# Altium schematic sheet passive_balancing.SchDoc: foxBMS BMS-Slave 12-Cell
size A3; DocumentNumber: 5; SheetNumber: 5; SheetTotal: 15; AUTHOR: Fraunhofer IISB foxBMS Team; SheetDescription: Passive Cell Balancing
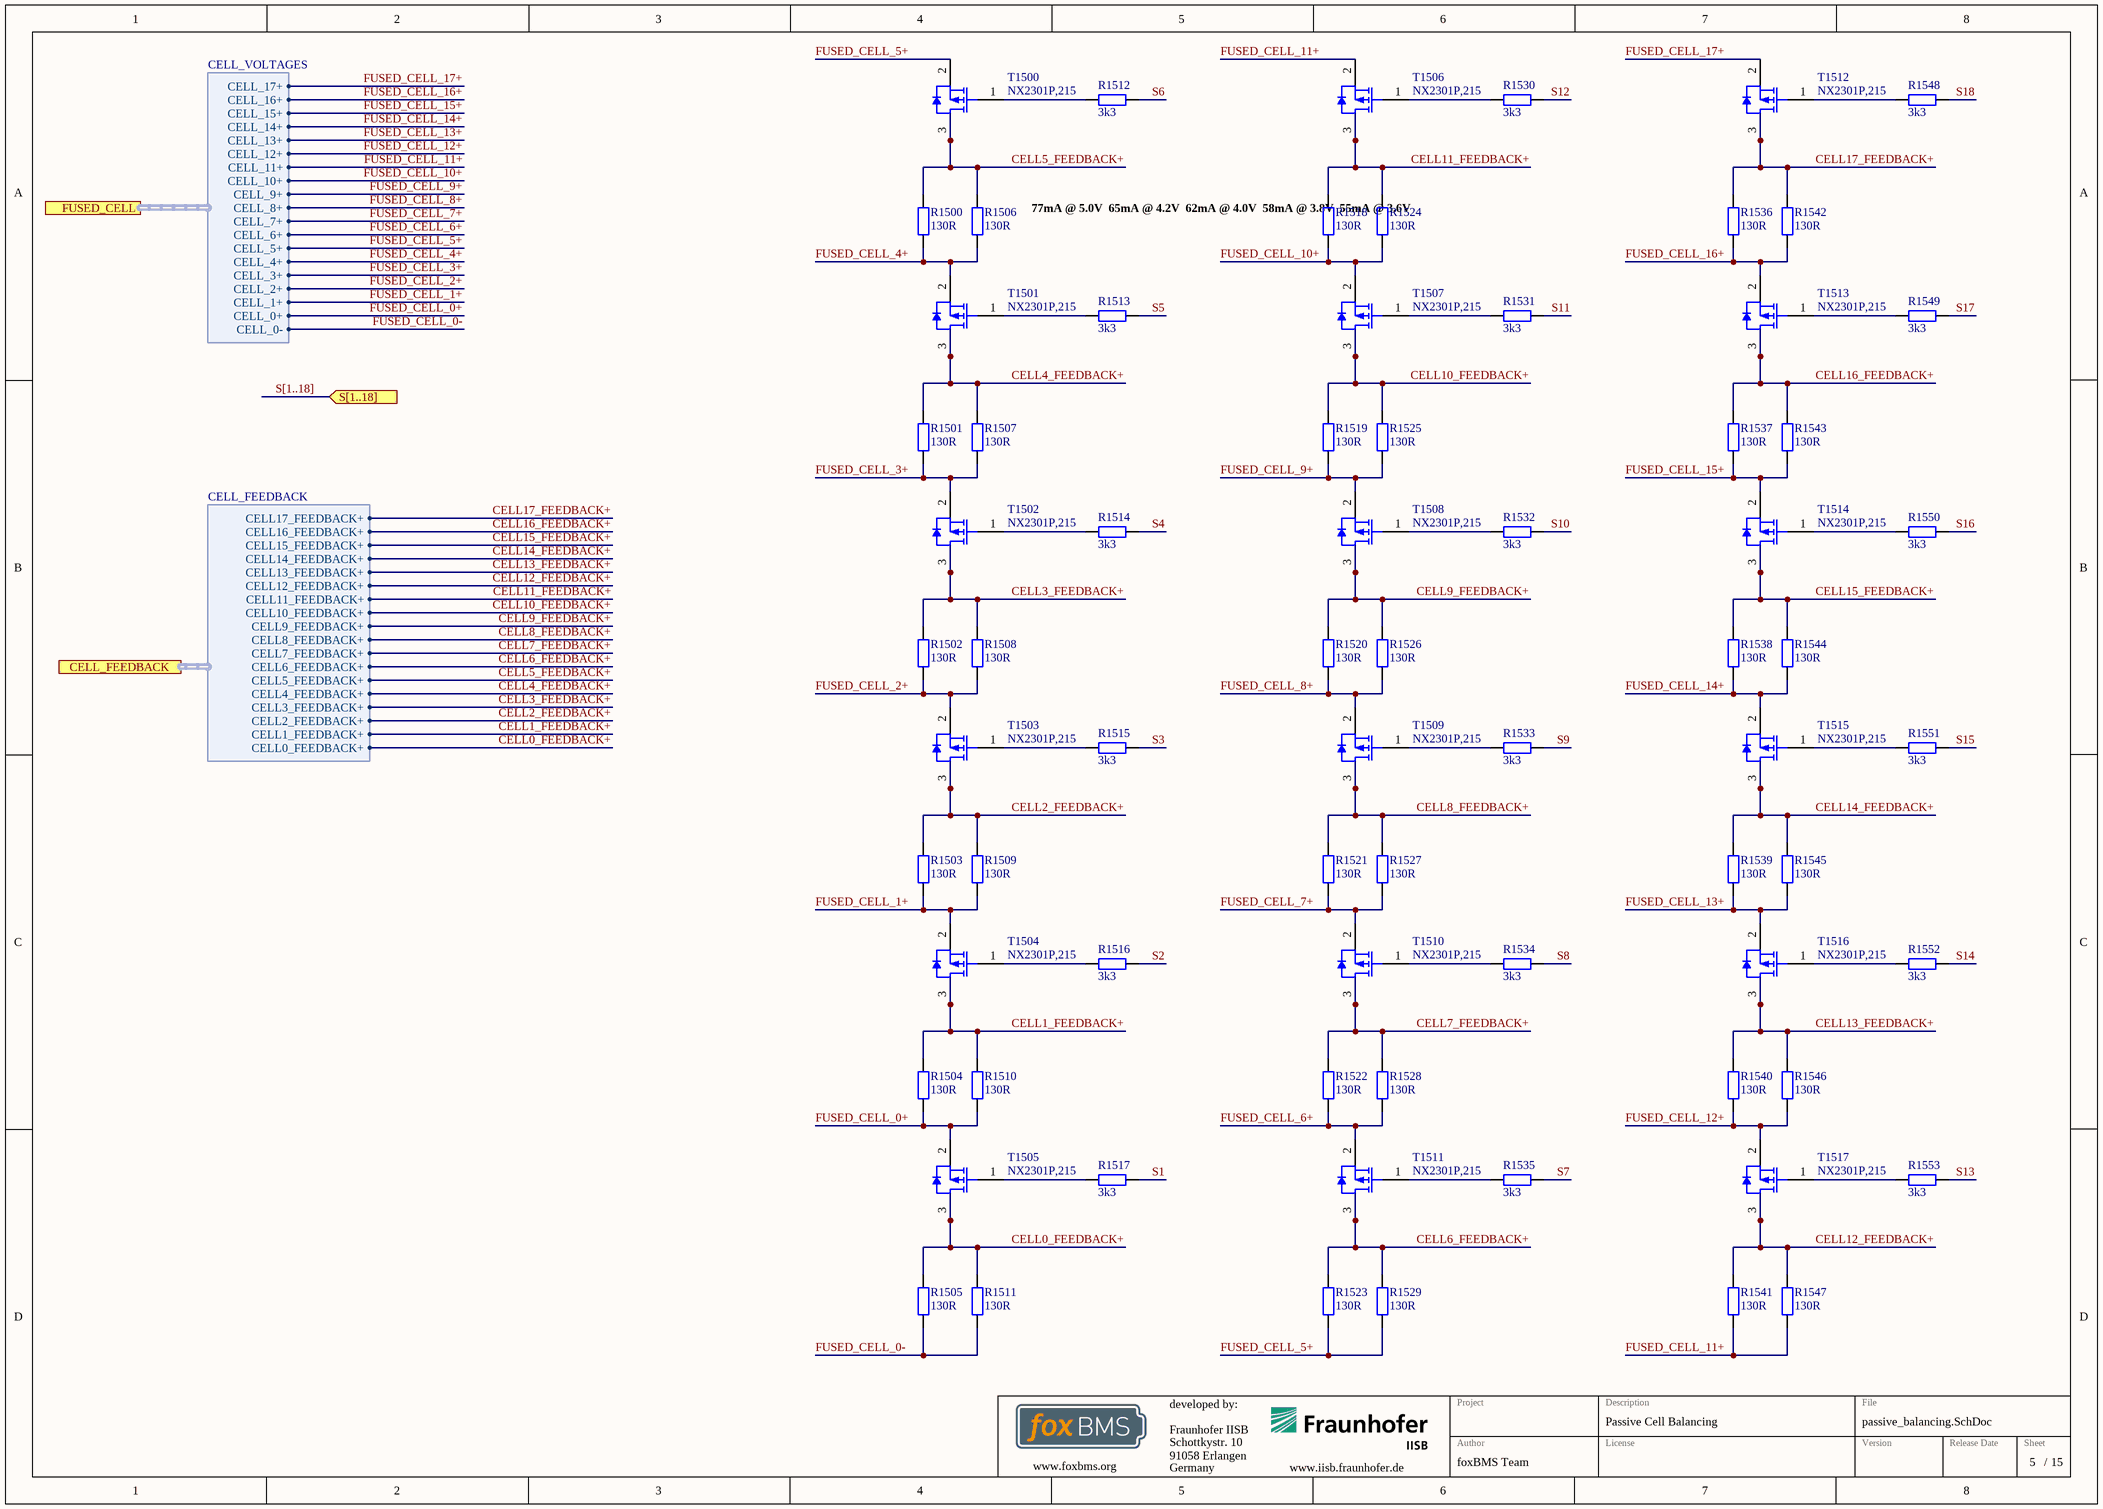
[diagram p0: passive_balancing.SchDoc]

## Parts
R1500  130R  [RESC5025X07N]
R1501  130R  [RESC5025X07N]
R1502  130R  [RESC5025X07N]
R1503  130R  [RESC5025X07N]
R1504  130R  [RESC5025X07N]
R1505  130R  [RESC5025X07N]
R1506  130R  [RESC5025X07N]
R1507  130R  [RESC5025X07N]
R1508  130R  [RESC5025X07N]
R1509  130R  [RESC5025X07N]
R1510  130R  [RESC5025X07N]
R1511  130R  [RESC5025X07N]
R1512  3k3  [RESC1608X05N]
R1513  3k3  [RESC1608X05N]
R1514  3k3  [RESC1608X05N]
R1515  3k3  [RESC1608X05N]
R1516  3k3  [RESC1608X05N]
R1517  3k3  [RESC1608X05N]
R1518  130R  [RESC5025X07N]
R1519  130R  [RESC5025X07N]
R1520  130R  [RESC5025X07N]
R1521  130R  [RESC5025X07N]
R1522  130R  [RESC5025X07N]
R1523  130R  [RESC5025X07N]
R1524  130R  [RESC5025X07N]
R1525  130R  [RESC5025X07N]
R1526  130R  [RESC5025X07N]
R1527  130R  [RESC5025X07N]
R1528  130R  [RESC5025X07N]
R1529  130R  [RESC5025X07N]
R1530  3k3  [RESC1608X05N]
R1531  3k3  [RESC1608X05N]
R1532  3k3  [RESC1608X05N]
R1533  3k3  [RESC1608X05N]
R1534  3k3  [RESC1608X05N]
R1535  3k3  [RESC1608X05N]
R1536  130R  [RESC5025X07N]
R1537  130R  [RESC5025X07N]
R1538  130R  [RESC5025X07N]
R1539  130R  [RESC5025X07N]
R1540  130R  [RESC5025X07N]
R1541  130R  [RESC5025X07N]
R1542  130R  [RESC5025X07N]
R1543  130R  [RESC5025X07N]
R1544  130R  [RESC5025X07N]
R1545  130R  [RESC5025X07N]
R1546  130R  [RESC5025X07N]
R1547  130R  [RESC5025X07N]
R1548  3k3  [RESC1608X05N]
R1549  3k3  [RESC1608X05N]
R1550  3k3  [RESC1608X05N]
R1551  3k3  [RESC1608X05N]
R1552  3k3  [RESC1608X05N]
R1553  3k3  [RESC1608X05N]
T1500  NX2301P,215  [NXP-SOT23_N]
T1501  NX2301P,215  [NXP-SOT23_N]
T1502  NX2301P,215  [NXP-SOT23_N]
T1503  NX2301P,215  [NXP-SOT23_N]
T1504  NX2301P,215  [NXP-SOT23_N]
T1505  NX2301P,215  [NXP-SOT23_N]
T1506  NX2301P,215  [NXP-SOT23_N]
T1507  NX2301P,215  [NXP-SOT23_N]
T1508  NX2301P,215  [NXP-SOT23_N]
T1509  NX2301P,215  [NXP-SOT23_N]
T1510  NX2301P,215  [NXP-SOT23_N]
T1511  NX2301P,215  [NXP-SOT23_N]
T1512  NX2301P,215  [NXP-SOT23_N]
T1513  NX2301P,215  [NXP-SOT23_N]
T1514  NX2301P,215  [NXP-SOT23_N]
T1515  NX2301P,215  [NXP-SOT23_N]
T1516  NX2301P,215  [NXP-SOT23_N]
T1517  NX2301P,215  [NXP-SOT23_N]

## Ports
CELL_FEEDBACK (harness CELL_FEEDBACK), FUSED_CELL (harness CELL_VOLTAGES), S[1..18] (in)

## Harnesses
CELL_FEEDBACK: CELL11_FEEDBACK+, CELL10_FEEDBACK+, CELL9_FEEDBACK+, CELL8_FEEDBACK+, CELL7_FEEDBACK+, CELL6_FEEDBACK+, CELL5_FEEDBACK+, CELL4_FEEDBACK+, CELL3_FEEDBACK+, CELL2_FEEDBACK+, CELL1_FEEDBACK+, CELL0_FEEDBACK+, CELL12_FEEDBACK+, CELL13_FEEDBACK+, CELL14_FEEDBACK+, CELL15_FEEDBACK+, CELL16_FEEDBACK+, CELL17_FEEDBACK+
CELL_VOLTAGES: CELL_0-, CELL_0+, CELL_1+, CELL_10+, CELL_11+, CELL_12+, CELL_13+, CELL_14+, CELL_15+, CELL_16+, CELL_17+, CELL_2+, CELL_3+, CELL_4+, CELL_5+, CELL_6+, CELL_7+, CELL_8+, CELL_9+

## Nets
CELL0_FEEDBACK+: R1505.2 R1511.2 T1505.3(D) ; port CELL_FEEDBACK.CELL0_FEEDBACK+
CELL1_FEEDBACK+: R1504.2 R1510.2 T1504.3(D) ; port CELL_FEEDBACK.CELL1_FEEDBACK+
CELL2_FEEDBACK+: R1503.2 R1509.2 T1503.3(D) ; port CELL_FEEDBACK.CELL2_FEEDBACK+
CELL3_FEEDBACK+: R1502.2 R1508.2 T1502.3(D) ; port CELL_FEEDBACK.CELL3_FEEDBACK+
CELL4_FEEDBACK+: R1501.2 R1507.2 T1501.3(D) ; port CELL_FEEDBACK.CELL4_FEEDBACK+
CELL5_FEEDBACK+: R1500.2 R1506.2 T1500.3(D) ; port CELL_FEEDBACK.CELL5_FEEDBACK+
CELL6_FEEDBACK+: R1523.2 R1529.2 T1511.3(D) ; port CELL_FEEDBACK.CELL6_FEEDBACK+
CELL7_FEEDBACK+: R1522.2 R1528.2 T1510.3(D) ; port CELL_FEEDBACK.CELL7_FEEDBACK+
CELL8_FEEDBACK+: R1521.2 R1527.2 T1509.3(D) ; port CELL_FEEDBACK.CELL8_FEEDBACK+
CELL9_FEEDBACK+: R1520.2 R1526.2 T1508.3(D) ; port CELL_FEEDBACK.CELL9_FEEDBACK+
CELL10_FEEDBACK+: R1519.2 R1525.2 T1507.3(D) ; port CELL_FEEDBACK.CELL10_FEEDBACK+
CELL11_FEEDBACK+: R1518.2 R1524.2 T1506.3(D) ; port CELL_FEEDBACK.CELL11_FEEDBACK+
CELL12_FEEDBACK+: R1541.2 R1547.2 T1517.3(D) ; port CELL_FEEDBACK.CELL12_FEEDBACK+
CELL13_FEEDBACK+: R1540.2 R1546.2 T1516.3(D) ; port CELL_FEEDBACK.CELL13_FEEDBACK+
CELL14_FEEDBACK+: R1539.2 R1545.2 T1515.3(D) ; port CELL_FEEDBACK.CELL14_FEEDBACK+
CELL15_FEEDBACK+: R1538.2 R1544.2 T1514.3(D) ; port CELL_FEEDBACK.CELL15_FEEDBACK+
CELL16_FEEDBACK+: R1537.2 R1543.2 T1513.3(D) ; port CELL_FEEDBACK.CELL16_FEEDBACK+
CELL17_FEEDBACK+: R1536.2 R1542.2 T1512.3(D) ; port CELL_FEEDBACK.CELL17_FEEDBACK+
FUSED_CELL_0+: R1504.1 R1510.1 T1505.2(S) ; port FUSED_CELL.CELL_0+
FUSED_CELL_0-: R1505.1 R1511.1 ; port FUSED_CELL.CELL_0-
FUSED_CELL_1+: R1503.1 R1509.1 T1504.2(S) ; port FUSED_CELL.CELL_1+
FUSED_CELL_2+: R1502.1 R1508.1 T1503.2(S) ; port FUSED_CELL.CELL_2+
FUSED_CELL_3+: R1501.1 R1507.1 T1502.2(S) ; port FUSED_CELL.CELL_3+
FUSED_CELL_4+: R1500.1 R1506.1 T1501.2(S) ; port FUSED_CELL.CELL_4+
FUSED_CELL_5+: R1523.1 R1529.1 T1500.2(S) ; port FUSED_CELL.CELL_5+
FUSED_CELL_6+: R1522.1 R1528.1 T1511.2(S) ; port FUSED_CELL.CELL_6+
FUSED_CELL_7+: R1521.1 R1527.1 T1510.2(S) ; port FUSED_CELL.CELL_7+
FUSED_CELL_8+: R1520.1 R1526.1 T1509.2(S) ; port FUSED_CELL.CELL_8+
FUSED_CELL_9+: R1519.1 R1525.1 T1508.2(S) ; port FUSED_CELL.CELL_9+
FUSED_CELL_10+: R1518.1 R1524.1 T1507.2(S) ; port FUSED_CELL.CELL_10+
FUSED_CELL_11+: R1541.1 R1547.1 T1506.2(S) ; port FUSED_CELL.CELL_11+
FUSED_CELL_12+: R1540.1 R1546.1 T1517.2(S) ; port FUSED_CELL.CELL_12+
FUSED_CELL_13+: R1539.1 R1545.1 T1516.2(S) ; port FUSED_CELL.CELL_13+
FUSED_CELL_14+: R1538.1 R1544.1 T1515.2(S) ; port FUSED_CELL.CELL_14+
FUSED_CELL_15+: R1537.1 R1543.1 T1514.2(S) ; port FUSED_CELL.CELL_15+
FUSED_CELL_16+: R1536.1 R1542.1 T1513.2(S) ; port FUSED_CELL.CELL_16+
FUSED_CELL_17+: T1512.2(S) ; port FUSED_CELL.CELL_17+
S1: R1517.2
S2: R1516.2
S3: R1515.2
S4: R1514.2
S5: R1513.2
S6: R1512.2
S7: R1535.2
S8: R1534.2
S9: R1533.2
S10: R1532.2
S11: R1531.2
S12: R1530.2
S13: R1553.2
S14: R1552.2
S15: R1551.2
S16: R1550.2
S17: R1549.2
S18: R1548.2
NetR1512_1: R1512.1 T1500.1(G)
NetR1513_1: R1513.1 T1501.1(G)
NetR1514_1: R1514.1 T1502.1(G)
NetR1515_1: R1515.1 T1503.1(G)
NetR1516_1: R1516.1 T1504.1(G)
NetR1517_1: R1517.1 T1505.1(G)
NetR1530_1: R1530.1 T1506.1(G)
NetR1531_1: R1531.1 T1507.1(G)
NetR1532_1: R1532.1 T1508.1(G)
NetR1533_1: R1533.1 T1509.1(G)
NetR1534_1: R1534.1 T1510.1(G)
NetR1535_1: R1535.1 T1511.1(G)
NetR1548_1: R1548.1 T1512.1(G)
NetR1549_1: R1549.1 T1513.1(G)
NetR1550_1: R1550.1 T1514.1(G)
NetR1551_1: R1551.1 T1515.1(G)
NetR1552_1: R1552.1 T1516.1(G)
NetR1553_1: R1553.1 T1517.1(G)

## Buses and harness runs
bus S[1..18] = port S[1..18]

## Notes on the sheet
- 77mA @ 5.0V
  65mA @ 4.2V
  62mA @ 4.0V
  58mA @ 3.8V
  55mA @ 3.6V

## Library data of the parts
R1500-R1511 R1518-R1529 R1536-R1547 = gen_R_130R_2010: SMD Resistor 130R 2010; Tolerance: 5%; Power: 0.75W; Case EIA: 2010; Case Metric: 5025; Maximum Working Voltage: 400V; PnP Package: R_2010; Automotive Qualified: True
R1512-R1517 R1530-R1535 R1548-R1553 = gen_R_3k3_0603: SMD Resistor 3k3 0603; Tolerance: 1%; Power: 0.1W; Case EIA: 0603; Case Metric: 1608; Maximum Working Voltage: 75V; PnP Package: R_0603; Automotive Qualified: True
T1500-T1517 = CMP-1259-00090-1: P-Channel Trench MOSFET, -20 V, -2 A, -55 to 150 degC, 3-Pin SOT23, Tape and Reel; Manufacturer: NXP Semiconductors; VGSth [typ] (V): -0.75; Channel Type: P; Packing: Tape & Reel; Automotive Qualified: Y; IDM [max] (A): -6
